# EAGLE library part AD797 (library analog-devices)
Ultralow Distortion, Ultralow Noise Op Amp Source: http://www.analog.com/static/imported-files/data_sheets/AD797.pdf
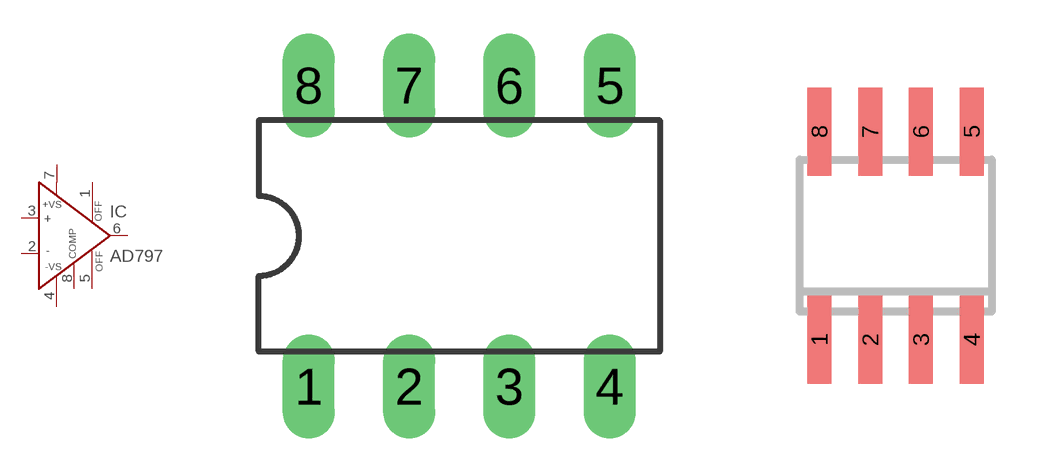
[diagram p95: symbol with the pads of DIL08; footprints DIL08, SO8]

Designator prefix IC

## AD797N (MF: ALTERA CORPORATION; MPN: AD797ANZ; OC_FARNELL: 9603778; OC_NEWARK: 59K6088)  [DIL08]
1  OFF  pas
2  IN-  in
3  IN+  in
4  -VS  in
5  OFF  pas
6  OUT  out
7  +VS  in
8  COMP  pas

## AD797R (MF: ALTERA CORPORATION; MPN: AD797ARZ; OC_FARNELL: 9426450; OC_NEWARK: 88H0085)  [SO8]
Pads as for DIL08

## Footprint DIL08 (pad centres in mm)
Dual In Line Package
drill 0.813 long: 1 -3.81,-3.81; 2 -1.27,-3.81; 3 1.27,-3.81; 4 3.81,-3.81; 5 3.81,3.81; 6 1.27,3.81; 7 -1.27,3.81; 8 -3.81,3.81

## Footprint SO8 (pad centres in mm)
8-Lead Small Outline IC (SO-8) Source: http://www.analog.com/UploadedFiles/Data_Sheets/703465986AD8611_2_0.pdf
smd 0.6 x 2.2: 1 -1.905,-2.6; 2 -0.635,-2.6; 3 0.635,-2.6; 4 1.905,-2.6; 5 1.905,2.6; 6 0.635,2.6; 7 -0.635,2.6; 8 -1.905,2.6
